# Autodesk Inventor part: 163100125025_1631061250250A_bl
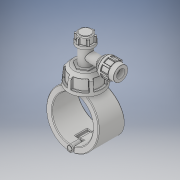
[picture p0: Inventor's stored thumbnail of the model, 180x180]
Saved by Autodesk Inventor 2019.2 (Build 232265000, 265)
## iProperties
Created: 2022-02
Part Number: 163100125025_1631061250250A_bl
Material: Generic
Description: Plassadle Tapper 122x25
Document SubType Name: Modeling
Designer: comp2
Density: 1 g/cm^3
Appearance: Default
Author: comp2
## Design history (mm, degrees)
derived "16310.ipt"
feature "Solid1::16310.ipt" dims "ScaleForDerivedMember" = 10
feature "Solid2::16310.ipt" dims "ScaleForDerivedMember" = 10
feature "Solid3::16310.ipt" dims "ScaleForDerivedMember" = 10
feature "Solid4::16310.ipt" dims "ScaleForDerivedMember" = 10
tag "TaggingFeature1"
body "Solid1"
body "Solid2"
body "Solid3"
body "Solid4"
other parameters: "d" = 122 [user parameter], "d1" = 25 [user parameter], "B" = 157 [user parameter], "E_" = 54 [user parameter], "E1" = 102 [user parameter], "H2" = 144 [user parameter], "H3" = 106 [user parameter], "H_costum" = 52 [user parameter], "d0" = 122 [user parameter], "d2" = 157 [user parameter], "d3" = 61 [user parameter], "d7" = 149.15 [user parameter], "d8" = 85 deg [user parameter], "d9" = 45 deg [user parameter], "d10" = 102 [user parameter], "d11" = 52 [user parameter], "d12" = 36.4 [user parameter], "d13" = 35.7 [user parameter], "d14" = 55.08 [user parameter], "d15" = 2.6 [user parameter], "d16" = 2 [user parameter], "d17" = 2 [user parameter], "d18" = 31.2 [user parameter], "d19" = 7.8 [user parameter], "d20" = 1 [user parameter], "d21" = 30.6 [user parameter], "d22" = 1 [user parameter], "d23" = 15.6 [user parameter], "d24" = 106 [user parameter], "d27" = 144 [user parameter], "d29" = 54 [user parameter], "d31" = 43.2 [user parameter], "d32" = 42.4 [user parameter], "d33" = 14.84 [user parameter], "d34" = 93 deg [user parameter], "d35" = 2 [user parameter], "d36" = 4 [user parameter], "d39" = 45 deg [user parameter], "d40" = 4 [user parameter], "d41" = 5 [user parameter], "d42" = 3.5 [user parameter], "d46" = 51 [user parameter], "d47" = 27 [user parameter], "d48" = 52 [user parameter], "d49" = 3.14 [user parameter], "d51" = 0 [user parameter], "d52" = 24.5 [user parameter], "d53" = 86.35 [user parameter], "d54" = 35 [user parameter], "d55" = 0 [user parameter], "d59" = 0 [user parameter], "d61" = 0 [user parameter], "d62" = 35 [user parameter], "d63" = 0 [user parameter], "d65" = 0 [user parameter], "d67" = 0 [user parameter], "d69" = 0 [user parameter], "d70" = 1 [user parameter], "d71" = 96 [user parameter], "d72" = 0 [user parameter], "d73" = 2 [user parameter], "d77" = 25 [user parameter], "d78" = 86.7 [user parameter], "d79" = 5.1 [user parameter], "d80" = 60 deg [user parameter], "d81" = 5.1 [user parameter], "d84" = 0 [user parameter], "d85" = 1 [user parameter], "d87" = 360 deg [user parameter], "d90" = 0 [user parameter], "d91" = 1 [user parameter], "d93" = 60 deg [user parameter], "d94" = 3.06 [user parameter], "d95" = 3.06 [user parameter], "d97" = 0 [user parameter], "d98" = 0.5 [user parameter], "d100" = 360 deg [user parameter], "d102" = 2 [user parameter], "d105" = 0 [user parameter], "d106" = 45 deg [user parameter], "d107" = 2.7 [user parameter], "d108" = 2.7 [user parameter], "d109" = 2.95332 [user parameter], "d110" = -8 [user parameter], "d112" = 0 [user parameter], "d113" = 0.5 [user parameter], "d115" = 360 deg [user parameter], "d117" = 0.5 [user parameter]
